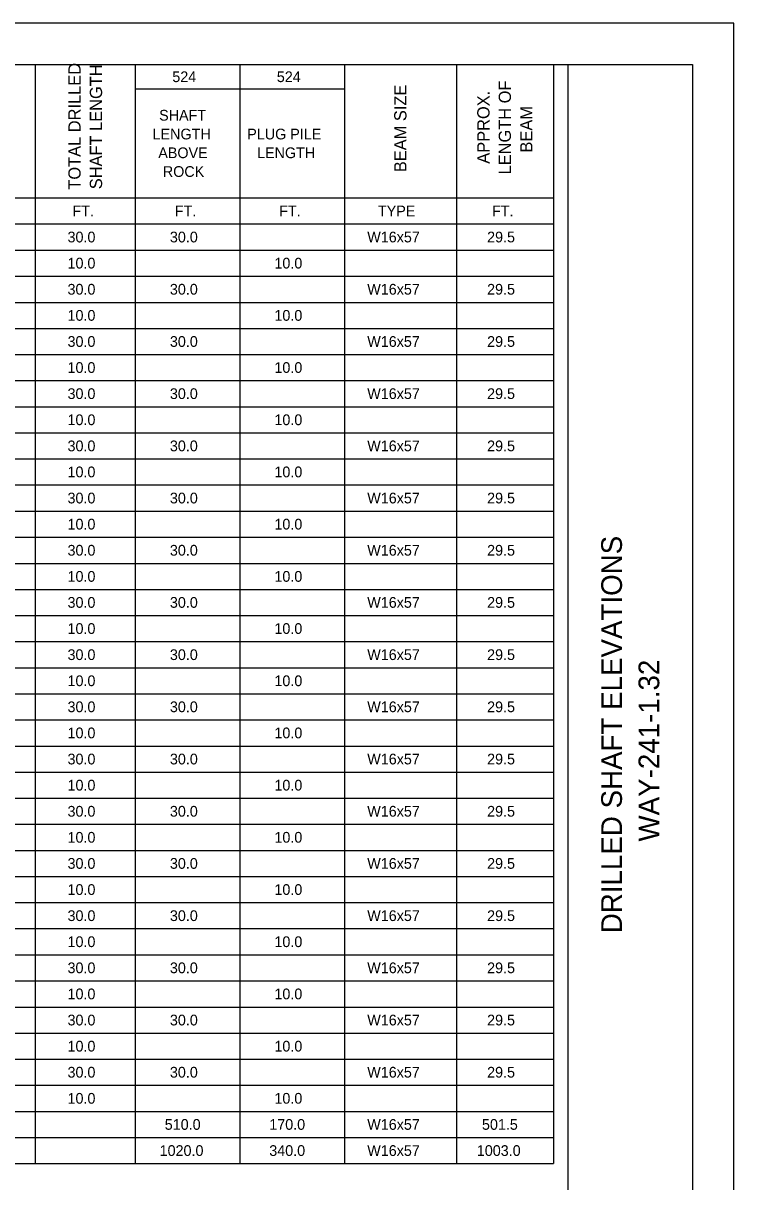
# Model space of a CAD drawing. Extents: x 0.4 to 34.4, y -28 to -6.
# Drawn here: x 25.78 to 34.35, y -19.95 to -5.97 of the extents above; entities that cross this region are included whole.
import ezdxf

# ---------------------------------------------------------------- set-up
doc = ezdxf.new("R2010")
doc.units = 0
for name, color, linetype in [('Default', 7, 'Continuous'), ('SH_Border', 7, 'Continuous'), ('SH_Cut_Line', 7, 'Continuous'), ('SH_Data', 7, 'Continuous')]:
    doc.layers.add(name, color=color, linetype=linetype)

msp = doc.modelspace()

# ---------------------------------------------------------------- linework, layer by layer
at = {"layer": 'Default'}
for p, q in [((21.702, -6.471), (32.174, -6.471)), ((25.922, -6.471), (25.922, -9.023)), ((27.131, -6.471), (27.131, -9.023)), ((28.392, -6.471), (28.392, -9.023)), ((29.653, -6.471), (29.653, -9.023)), ((31.004, -6.471), (31.004, -9.023)), ((32.174, -6.471), (32.174, -9.023)), ((27.131, -6.763), (29.653, -6.763)), ((21.702, -8.079), (32.174, -8.079)), ((21.702, -8.393), (32.174, -8.393)), ((21.702, -8.708), (32.174, -8.708)), ((21.702, -9.023), (32.174, -9.023)), ((25.922, -9.023), (25.922, -9.338)), ((27.131, -9.023), (27.131, -9.338)), ((28.392, -9.023), (28.392, -9.338)), ((29.653, -9.023), (29.653, -9.338)), ((31.004, -9.023), (31.004, -9.338)), ((32.174, -9.023), (32.174, -9.338)), ((21.702, -9.338), (32.174, -9.338)), ((25.922, -9.338), (25.922, -9.653)), ((27.131, -9.338), (27.131, -9.653)), ((28.392, -9.338), (28.392, -9.653)), ((29.653, -9.338), (29.653, -9.653)), ((31.004, -9.338), (31.004, -9.653)), ((32.174, -9.338), (32.174, -9.653)), ((21.702, -9.653), (32.174, -9.653)), ((25.922, -9.653), (25.922, -11.541)), ((27.131, -9.653), (27.131, -11.541)), ((28.392, -9.653), (28.392, -11.541)), ((29.653, -9.653), (29.653, -11.541)), ((31.004, -9.653), (31.004, -11.541)), ((32.174, -9.653), (32.174, -11.541)), ((21.702, -9.967), (32.174, -9.967)), ((21.702, -10.282), (32.174, -10.282)), ((21.702, -10.597), (32.174, -10.597)), ((21.702, -10.912), (32.174, -10.912)), ((21.702, -11.226), (32.174, -11.226)), ((21.702, -11.541), (32.174, -11.541)), ((25.922, -11.541), (25.922, -11.856)), ((27.131, -11.541), (27.131, -11.856)), ((28.392, -11.541), (28.392, -11.856)), ((29.653, -11.541), (29.653, -11.856)), ((31.004, -11.541), (31.004, -11.856)), ((32.174, -11.541), (32.174, -11.856)), ((21.702, -11.856), (32.174, -11.856)), ((25.922, -11.856), (25.922, -12.171)), ((27.131, -11.856), (27.131, -12.171)), ((28.392, -11.856), (28.392, -12.171)), ((29.653, -11.856), (29.653, -12.171)), ((31.004, -11.856), (31.004, -12.171)), ((32.174, -11.856), (32.174, -12.171)), ((21.702, -12.171), (32.174, -12.171)), ((25.922, -12.171), (25.922, -16.892)), ((27.131, -12.171), (27.131, -16.892)), ((28.392, -12.171), (28.392, -16.892)), ((29.653, -12.171), (29.653, -16.892)), ((31.004, -12.171), (31.004, -16.892)), ((32.174, -12.171), (32.174, -16.892)), ((21.702, -12.486), (32.174, -12.486)), ((21.702, -12.8), (32.174, -12.8)), ((21.702, -13.115), (32.174, -13.115)), ((21.702, -13.43), (32.174, -13.43)), ((21.702, -13.745), (32.174, -13.745)), ((21.702, -14.059), (32.174, -14.059)), ((21.702, -14.374), (32.174, -14.374)), ((21.702, -14.689), (32.174, -14.689)), ((21.702, -15.004), (32.174, -15.004)), ((21.702, -15.319), (32.174, -15.319)), ((21.702, -15.633), (32.174, -15.633)), ((21.702, -15.948), (32.174, -15.948)), ((21.702, -16.263), (32.174, -16.263)), ((21.702, -16.578), (32.174, -16.578)), ((21.702, -16.892), (32.174, -16.892)), ((25.922, -16.892), (25.922, -17.207)), ((27.131, -16.892), (27.131, -17.207)), ((28.392, -16.892), (28.392, -17.207)), ((29.653, -16.892), (29.653, -17.207)), ((31.004, -16.892), (31.004, -17.207)), ((32.174, -16.892), (32.174, -17.207)), ((21.702, -17.207), (32.174, -17.207)), ((25.922, -17.207), (25.922, -17.522)), ((27.131, -17.207), (27.131, -17.522)), ((28.392, -17.207), (28.392, -17.522)), ((29.653, -17.207), (29.653, -17.522)), ((31.004, -17.207), (31.004, -17.522)), ((32.174, -17.207), (32.174, -17.522)), ((21.702, -17.522), (32.174, -17.522)), ((25.922, -17.522), (25.922, -17.837)), ((27.131, -17.522), (27.131, -17.837)), ((28.392, -17.522), (28.392, -17.837)), ((29.653, -17.522), (29.653, -17.837)), ((31.004, -17.522), (31.004, -17.837)), ((32.174, -17.522), (32.174, -17.837)), ((21.702, -17.837), (32.174, -17.837)), ((25.922, -17.837), (25.922, -18.466)), ((27.131, -17.837), (27.131, -18.466)), ((28.392, -17.837), (28.392, -18.466)), ((29.653, -17.837), (29.653, -18.466)), ((31.004, -17.837), (31.004, -18.466)), ((32.174, -17.837), (32.174, -18.466)), ((21.702, -18.152), (32.174, -18.152)), ((21.702, -18.466), (32.174, -18.466)), ((25.922, -18.466), (25.922, -18.781)), ((27.131, -18.466), (27.131, -18.781)), ((28.392, -18.466), (28.392, -18.781)), ((29.653, -18.466), (29.653, -18.781)), ((31.004, -18.466), (31.004, -18.781)), ((32.174, -18.466), (32.174, -18.781)), ((21.702, -18.781), (32.174, -18.781)), ((25.922, -18.781), (25.922, -19.096)), ((27.131, -18.781), (27.131, -19.096)), ((28.392, -18.781), (28.392, -19.096)), ((29.653, -18.781), (29.653, -19.096)), ((31.004, -18.781), (31.004, -19.096)), ((32.174, -18.781), (32.174, -19.096)), ((21.702, -19.096), (32.174, -19.096)), ((25.922, -19.096), (25.922, -19.411)), ((27.131, -19.096), (27.131, -19.411)), ((28.392, -19.096), (28.392, -19.411)), ((29.653, -19.096), (29.653, -19.411)), ((31.004, -19.096), (31.004, -19.411)), ((32.174, -19.096), (32.174, -19.411)), ((21.702, -19.411), (32.174, -19.411)), ((25.922, -19.411), (25.922, -19.725)), ((27.131, -19.411), (27.131, -19.725)), ((28.392, -19.411), (28.392, -19.725)), ((29.653, -19.411), (29.653, -19.725)), ((31.004, -19.411), (31.004, -19.725)), ((32.174, -19.411), (32.174, -19.725)), ((21.702, -19.725), (32.174, -19.725))]:
    msp.add_line(p, q, dxfattribs=at)
at = {"layer": 'SH_Border'}
msp.add_line((32.352, -27.471), (32.352, -6.471), dxfattribs=at)
msp.add_lwpolyline([(1.852, -6.471), (33.852, -6.471), (33.852, -27.471), (1.852, -27.471)], close=True, dxfattribs=at)
at = {"layer": 'SH_Cut_Line'}
msp.add_lwpolyline([(0.352, -27.971), (34.352, -27.971), (34.352, -5.971), (0.352, -5.971)], close=True, dxfattribs=at)

# ---------------------------------------------------------------- texts
at = {"layer": 'Default'}
for s, height, p in [('TOTAL DRILLED ', 0.14795, (26.471, -7.979)), ('SHAFT LENGTH', 0.14795, (26.73, -7.974)), ('LENGTH OF ', 0.1479, (31.663, -7.795)), ('BEAM SIZE', 0.1479, (30.402, -7.768)), ('APPROX. ', 0.1479, (31.404, -7.666)), ('BEAM', 0.1479, (31.922, -7.531))]:
    msp.add_text(s, height=height, rotation=90, dxfattribs=at).set_placement(p)
for s, height, p in [('524', 0.1293, (27.577, -6.682)), ('524', 0.1293, (28.838, -6.682)), ('SHAFT ', 0.1293, (27.418, -7.146)), ('LENGTH                             ', 0.12928, (27.339, -7.373)), ('PLUG PILE ', 0.1293, (28.481, -7.373)), ('ABOVE ', 0.1293, (27.408, -7.599)), ('LENGTH', 0.1293, (28.6, -7.599)), ('ROCK', 0.1293, (27.463, -7.825)), ('FT.', 0.1293, (26.372, -8.301)), ('FT.', 0.1293, (27.607, -8.301)), ('FT.', 0.1293, (28.868, -8.301)), ('TYPE', 0.1293, (30.058, -8.301)), ('FT.', 0.1293, (31.434, -8.301)), ('30.0', 0.1293, (26.313, -8.615)), ('30.0', 0.1293, (27.548, -8.615)), ('W16x57', 0.1293, (29.929, -8.615)), ('29.5', 0.1293, (31.375, -8.615)), ('10.0', 0.1293, (26.313, -8.93)), ('10.0', 0.1293, (28.809, -8.93)), ('30.0', 0.1293, (26.313, -9.245)), ('30.0', 0.1293, (27.548, -9.245)), ('W16x57', 0.1293, (29.929, -9.245)), ('29.5', 0.1293, (31.375, -9.245)), ('10.0', 0.1293, (26.313, -9.56)), ('10.0', 0.1293, (28.809, -9.56)), ('30.0', 0.1293, (26.313, -9.875)), ('30.0', 0.1293, (27.548, -9.875)), ('W16x57', 0.1293, (29.929, -9.875)), ('29.5', 0.1293, (31.375, -9.875)), ('10.0', 0.1293, (26.313, -10.189)), ('10.0', 0.1293, (28.809, -10.189)), ('30.0', 0.1293, (26.313, -10.504)), ('30.0', 0.1293, (27.548, -10.504)), ('W16x57', 0.1293, (29.929, -10.504)), ('29.5', 0.1293, (31.375, -10.504)), ('10.0', 0.1293, (26.313, -10.819)), ('10.0', 0.1293, (28.809, -10.819)), ('30.0', 0.1293, (26.313, -11.134)), ('30.0', 0.1293, (27.548, -11.134)), ('W16x57', 0.1293, (29.929, -11.134)), ('29.5', 0.1293, (31.375, -11.134)), ('10.0', 0.1293, (26.313, -11.448)), ('10.0', 0.1293, (28.809, -11.448)), ('30.0', 0.1293, (26.313, -11.763)), ('30.0', 0.1293, (27.548, -11.763)), ('W16x57', 0.1293, (29.929, -11.763)), ('29.5', 0.1293, (31.375, -11.763)), ('10.0', 0.1293, (26.313, -12.078)), ('10.0', 0.1293, (28.809, -12.078)), ('30.0', 0.1293, (26.313, -12.393)), ('30.0', 0.1293, (27.548, -12.393)), ('W16x57', 0.1293, (29.929, -12.393)), ('29.5', 0.1293, (31.375, -12.393)), ('10.0', 0.1293, (26.313, -12.708)), ('10.0', 0.1293, (28.809, -12.708)), ('30.0', 0.1293, (26.313, -13.022)), ('30.0', 0.1293, (27.548, -13.022)), ('W16x57', 0.1293, (29.929, -13.022)), ('29.5', 0.1293, (31.375, -13.022)), ('10.0', 0.1293, (26.313, -13.337)), ('10.0', 0.1293, (28.809, -13.337)), ('30.0', 0.1293, (26.313, -13.652)), ('30.0', 0.1293, (27.548, -13.652)), ('W16x57', 0.1293, (29.929, -13.652)), ('29.5', 0.1293, (31.375, -13.652)), ('10.0', 0.1293, (26.313, -13.967)), ('10.0', 0.1293, (28.809, -13.967)), ('30.0', 0.1293, (26.313, -14.281)), ('30.0', 0.1293, (27.548, -14.281)), ('W16x57', 0.1293, (29.929, -14.281)), ('29.5', 0.1293, (31.375, -14.281)), ('10.0', 0.1293, (26.313, -14.596)), ('10.0', 0.1293, (28.809, -14.596)), ('30.0', 0.1293, (26.313, -14.911)), ('30.0', 0.1293, (27.548, -14.911)), ('W16x57', 0.1293, (29.929, -14.911)), ('29.5', 0.1293, (31.375, -14.911)), ('10.0', 0.1293, (26.313, -15.226)), ('10.0', 0.1293, (28.809, -15.226)), ('30.0', 0.1293, (26.313, -15.541)), ('30.0', 0.1293, (27.548, -15.541)), ('W16x57', 0.1293, (29.929, -15.541)), ('29.5', 0.1293, (31.375, -15.541)), ('10.0', 0.1293, (26.313, -15.855)), ('10.0', 0.1293, (28.809, -15.855)), ('30.0', 0.1293, (26.313, -16.17)), ('30.0', 0.1293, (27.548, -16.17)), ('W16x57', 0.1293, (29.929, -16.17)), ('29.5', 0.1293, (31.375, -16.17)), ('10.0', 0.1293, (26.313, -16.485)), ('10.0', 0.1293, (28.809, -16.485)), ('30.0', 0.1293, (26.313, -16.8)), ('30.0', 0.1293, (27.548, -16.8)), ('W16x57', 0.1293, (29.929, -16.8)), ('29.5', 0.1293, (31.375, -16.8)), ('10.0', 0.1293, (26.313, -17.114)), ('10.0', 0.1293, (28.809, -17.114)), ('30.0', 0.1293, (26.313, -17.429)), ('30.0', 0.1293, (27.548, -17.429)), ('W16x57', 0.1293, (29.929, -17.429)), ('29.5', 0.1293, (31.375, -17.429)), ('10.0', 0.1293, (26.313, -17.744)), ('10.0', 0.1293, (28.809, -17.744)), ('30.0', 0.1293, (26.313, -18.059)), ('30.0', 0.1293, (27.548, -18.059)), ('W16x57', 0.1293, (29.929, -18.059)), ('29.5', 0.1293, (31.375, -18.059)), ('10.0', 0.1293, (26.313, -18.374)), ('10.0', 0.1293, (28.809, -18.374)), ('30.0', 0.1293, (26.313, -18.688)), ('30.0', 0.1293, (27.548, -18.688)), ('W16x57', 0.1293, (29.929, -18.688)), ('29.5', 0.1293, (31.375, -18.688)), ('10.0', 0.1293, (26.313, -19.003)), ('10.0', 0.1293, (28.809, -19.003)), ('510.0', 0.1293, (27.486, -19.318)), ('170.0', 0.1293, (28.747, -19.318)), ('W16x57', 0.1293, (29.929, -19.318)), ('501.5', 0.1293, (31.313, -19.318)), ('1020.0', 0.1293, (27.424, -19.633)), ('340.0', 0.1293, (28.747, -19.633)), ('W16x57', 0.1293, (29.929, -19.633)), ('1003.0', 0.1293, (31.251, -19.633))]:
    msp.add_text(s, height=height, dxfattribs=at).set_placement(p)
at = {"layer": 'SH_Data'}
for s, p in [('DRILLED SHAFT ELEVATIONS', (33.002, -16.947)), ('WAY-241-1.32', (33.452, -15.841))]:
    msp.add_text(s, height=0.25, rotation=90, dxfattribs=at).set_placement(p)

doc.saveas('drawing.dxf')
